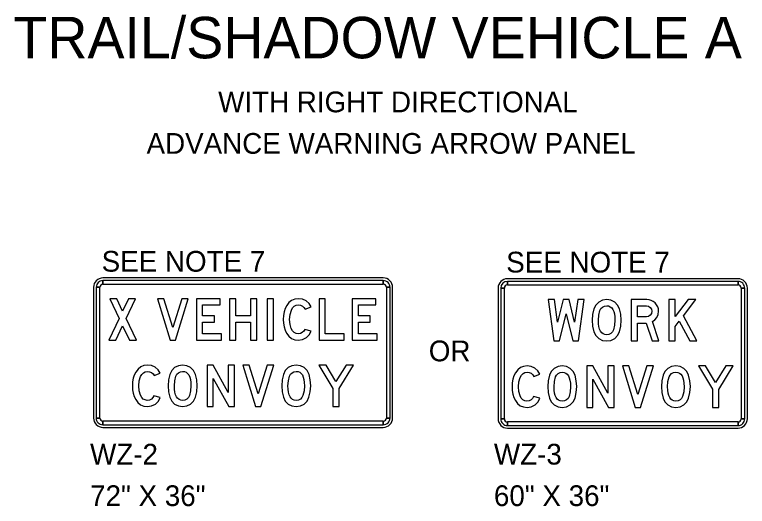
# Model space of a CAD drawing. Extents: x 1807779 to 1818251, y 673292 to 678849.
# Drawn here: x 1817413.4 to 1817625.1, y 677044.8 to 677187 of the extents above; entities that cross this region are included whole.
import ezdxf

# ---------------------------------------------------------------- set-up
doc = ezdxf.new("R2010")
doc.units = 0
doc.layers.add('DSN_RDWY_Drive', color=7, linetype='Continuous')

msp = doc.modelspace()

# ---------------------------------------------------------------- linework, layer by layer
at = {"layer": 'DSN_RDWY_Drive'}
for p, q in [((1817519.9, 677110.88), (1817438.9, 677110.88)), ((1817438.9, 677109.08), (1817438.9, 677110.13)), ((1817519.9, 677110.13), (1817519.9, 677109.08)), ((1817622.37, 677110.65), (1817555.77, 677110.65)), ((1817555.77, 677108.85), (1817555.77, 677109.9)), ((1817622.37, 677109.9), (1817622.37, 677108.85)), ((1817436.2, 677108.18), (1817436.2, 677070.38)), ((1817436.95, 677108.18), (1817438, 677108.18)), ((1817520.8, 677108.18), (1817521.85, 677108.18)), ((1817522.6, 677070.38), (1817522.6, 677108.18)), ((1817553.07, 677107.95), (1817553.07, 677070.15)), ((1817553.82, 677107.95), (1817554.87, 677107.95)), ((1817623.27, 677107.95), (1817624.32, 677107.95)), ((1817625.07, 677070.15), (1817625.07, 677107.95)), ((1817438, 677070.38), (1817436.95, 677070.38)), ((1817438.9, 677068.43), (1817438.9, 677069.48)), ((1817519.9, 677069.48), (1817519.9, 677068.43)), ((1817521.85, 677070.38), (1817520.8, 677070.38)), ((1817554.87, 677070.15), (1817553.82, 677070.15)), ((1817555.77, 677068.2), (1817555.77, 677069.25)), ((1817622.37, 677069.25), (1817622.37, 677068.2)), ((1817624.32, 677070.15), (1817623.27, 677070.15)), ((1817438.9, 677067.68), (1817519.9, 677067.68)), ((1817555.77, 677067.45), (1817622.37, 677067.45))]:
    msp.add_line(p, q, dxfattribs=at)
for points in [[(1817519.9, 677110.13), (1817438.9, 677110.13), (1817438.9, 677109.08), (1817519.9, 677109.08), (1817519.9, 677110.13)], [(1817622.37, 677109.9), (1817555.77, 677109.9), (1817555.77, 677108.85), (1817622.37, 677108.85), (1817622.37, 677109.9)], [(1817436.95, 677108.18), (1817436.95, 677070.38), (1817438, 677070.38), (1817438, 677108.18), (1817436.95, 677108.18)], [(1817521.85, 677070.38), (1817521.85, 677108.18), (1817520.8, 677108.18), (1817520.8, 677070.38), (1817521.85, 677070.38)], [(1817553.82, 677107.95), (1817553.82, 677070.15), (1817554.87, 677070.15), (1817554.87, 677107.95), (1817553.82, 677107.95)], [(1817624.32, 677070.15), (1817624.32, 677107.95), (1817623.27, 677107.95), (1817623.27, 677070.15), (1817624.32, 677070.15)], [(1817448.6, 677092.88), (1817445.61, 677099.16), (1817448.35, 677104.88), (1817446.34, 677104.88), (1817444.6, 677101.26), (1817442.88, 677104.88), (1817440.87, 677104.88), (1817443.6, 677099.15), (1817440.59, 677092.88), (1817442.59, 677092.88), (1817444.6, 677097.05), (1817446.59, 677092.88)], [(1817463.58, 677104.88), (1817461.69, 677104.88), (1817459.11, 677096.59), (1817456.54, 677104.88), (1817454.65, 677104.88), (1817458.37, 677092.88), (1817459.86, 677092.88)], [(1817473.15, 677094.69), (1817467.71, 677094.69), (1817467.71, 677098.09), (1817471.11, 677098.09), (1817471.11, 677099.9), (1817467.71, 677099.9), (1817467.71, 677103.07), (1817472.79, 677103.07), (1817472.79, 677104.88), (1817465.9, 677104.88), (1817465.9, 677092.88), (1817473.15, 677092.88)], [(1817483.38, 677092.88), (1817483.38, 677104.88), (1817481.57, 677104.88), (1817481.57, 677099.9), (1817477.27, 677099.9), (1817477.27, 677104.88), (1817475.46, 677104.88), (1817475.46, 677092.88), (1817477.27, 677092.88), (1817477.27, 677098.09), (1817481.57, 677098.09), (1817481.57, 677092.88)], [(1817488.15, 677092.88), (1817488.15, 677104.88), (1817486.34, 677104.88), (1817486.34, 677092.88)], [(1817499.03, 677095.54), (1817497.22, 677096), (1817496.95, 677095.48), (1817496.51, 677095.06), (1817495.95, 677094.78), (1817495.32, 677094.69), (1817494.69, 677094.79), (1817494.15, 677095.07), (1817493.7, 677095.55), (1817493.33, 677096.22), (1817492.96, 677097.45), (1817492.84, 677098.88), (1817492.96, 677100.31), (1817493.34, 677101.55), (1817493.72, 677102.21), (1817494.19, 677102.69), (1817494.74, 677102.97), (1817495.38, 677103.07), (1817495.98, 677102.98), (1817496.53, 677102.73), (1817496.98, 677102.34), (1817497.29, 677101.84), (1817499.03, 677102.52), (1817498.45, 677103.48), (1817497.59, 677104.23), (1817496.55, 677104.72), (1817495.41, 677104.88), (1817494.35, 677104.75), (1817493.43, 677104.38), (1817492.65, 677103.75), (1817491.99, 677102.88), (1817491.57, 677102.01), (1817491.27, 677101.06), (1817491.09, 677100.01), (1817491.02, 677098.89), (1817491.08, 677097.76), (1817491.26, 677096.72), (1817491.56, 677095.77), (1817491.98, 677094.9), (1817492.62, 677094.01), (1817493.4, 677093.39), (1817494.31, 677093), (1817495.35, 677092.88), (1817496.57, 677093.06), (1817497.67, 677093.62), (1817498.52, 677094.47)], [(1817508.59, 677092.88), (1817508.59, 677094.69), (1817503.15, 677094.69), (1817503.15, 677104.88), (1817501.34, 677104.88), (1817501.34, 677092.88)], [(1817518.15, 677094.69), (1817512.71, 677094.69), (1817512.71, 677098.09), (1817516.11, 677098.09), (1817516.11, 677099.9), (1817512.71, 677099.9), (1817512.71, 677103.07), (1817517.79, 677103.07), (1817517.79, 677104.88), (1817510.9, 677104.88), (1817510.9, 677092.88), (1817518.15, 677092.88)], [(1817577.93, 677104.64), (1817576.1, 677104.64), (1817575.18, 677098.07), (1817573.59, 677104.64), (1817571.84, 677104.64), (1817570.26, 677098.06), (1817569.34, 677104.64), (1817567.51, 677104.64), (1817569.19, 677092.65), (1817570.82, 677092.65), (1817572.72, 677100.54), (1817574.62, 677092.65), (1817576.25, 677092.65)], [(1817588.63, 677098.65), (1817588.51, 677100.36), (1817588.14, 677101.97), (1817587.6, 677103.05), (1817586.74, 677103.91), (1817585.66, 677104.46), (1817584.44, 677104.64), (1817583.22, 677104.46), (1817582.14, 677103.91), (1817581.28, 677103.05), (1817580.74, 677101.96), (1817580.37, 677100.35), (1817580.25, 677098.65), (1817580.37, 677096.95), (1817580.74, 677095.34), (1817581.28, 677094.25), (1817582.14, 677093.39), (1817583.22, 677092.83), (1817584.44, 677092.65), (1817585.65, 677092.83), (1817586.74, 677093.38), (1817587.59, 677094.24), (1817588.13, 677095.32), (1817588.5, 677096.93)], [(1817599.51, 677092.65), (1817597.62, 677098.25), (1817598.36, 677098.77), (1817598.93, 677099.49), (1817599.3, 677100.35), (1817599.43, 677101.27), (1817599.36, 677101.94), (1817599.18, 677102.56), (1817598.87, 677103.13), (1817598.43, 677103.65), (1817597.9, 677104.09), (1817597.33, 677104.4), (1817596.7, 677104.58), (1817596.03, 677104.64), (1817591.5, 677104.64), (1817591.5, 677092.65), (1817593.31, 677092.65), (1817593.31, 677097.85), (1817595.83, 677097.85), (1817597.6, 677092.65)], [(1817610.51, 677092.65), (1817606.61, 677099.96), (1817610.22, 677104.64), (1817607.93, 677104.64), (1817604.19, 677099.78), (1817604.19, 677104.64), (1817602.38, 677104.64), (1817602.38, 677092.65), (1817604.19, 677092.65), (1817604.19, 677096.82), (1817605.4, 677098.38), (1817608.46, 677092.65)], [(1817586.82, 677098.64), (1817586.71, 677097.19), (1817586.4, 677095.83), (1817586.11, 677095.27), (1817585.66, 677094.83), (1817585.09, 677094.55), (1817584.45, 677094.46), (1817583.89, 677094.52), (1817583.4, 677094.72), (1817582.99, 677095.04), (1817582.66, 677095.5), (1817582.4, 677096.09), (1817582.21, 677096.81), (1817582.1, 677097.66), (1817582.07, 677098.64), (1817582.17, 677100.1), (1817582.49, 677101.45), (1817582.78, 677102.01), (1817583.23, 677102.46), (1817583.8, 677102.74), (1817584.45, 677102.83), (1817585, 677102.77), (1817585.48, 677102.57), (1817585.89, 677102.24), (1817586.23, 677101.79), (1817586.48, 677101.2), (1817586.67, 677100.48), (1817586.78, 677099.62)], [(1817593.31, 677099.66), (1817593.31, 677102.83), (1817595.95, 677102.83), (1817596.53, 677102.71), (1817597.02, 677102.36), (1817597.35, 677101.85), (1817597.46, 677101.25), (1817597.35, 677100.64), (1817597.02, 677100.13), (1817596.53, 677099.78), (1817595.95, 677099.66)], [(1817455.44, 677076.34), (1817453.62, 677076.8), (1817453.36, 677076.28), (1817452.92, 677075.86), (1817452.35, 677075.58), (1817451.73, 677075.49), (1817451.1, 677075.59), (1817450.56, 677075.87), (1817450.1, 677076.35), (1817449.73, 677077.02), (1817449.36, 677078.25), (1817449.24, 677079.68), (1817449.37, 677081.12), (1817449.75, 677082.35), (1817450.13, 677083.01), (1817450.59, 677083.49), (1817451.14, 677083.77), (1817451.79, 677083.87), (1817452.39, 677083.78), (1817452.93, 677083.54), (1817453.39, 677083.14), (1817453.7, 677082.64), (1817455.44, 677083.32), (1817454.85, 677084.29), (1817454, 677085.04), (1817452.96, 677085.52), (1817451.82, 677085.68), (1817450.76, 677085.55), (1817449.84, 677085.18), (1817449.05, 677084.55), (1817448.4, 677083.68), (1817447.97, 677082.81), (1817447.67, 677081.86), (1817447.49, 677080.82), (1817447.43, 677079.69), (1817447.49, 677078.56), (1817447.67, 677077.52), (1817447.96, 677076.57), (1817448.39, 677075.7), (1817449.03, 677074.82), (1817449.8, 677074.19), (1817450.71, 677073.8), (1817451.76, 677073.68), (1817452.98, 677073.86), (1817454.07, 677074.42), (1817454.93, 677075.27)], [(1817466.12, 677079.69), (1817466, 677081.4), (1817465.63, 677083), (1817465.09, 677084.08), (1817464.23, 677084.94), (1817463.14, 677085.49), (1817461.92, 677085.68), (1817460.7, 677085.49), (1817459.62, 677084.94), (1817458.77, 677084.08), (1817458.23, 677082.99), (1817457.86, 677081.39), (1817457.74, 677079.69), (1817457.86, 677077.99), (1817458.23, 677076.38), (1817458.77, 677075.29), (1817459.62, 677074.43), (1817460.7, 677073.87), (1817461.92, 677073.68), (1817463.14, 677073.86), (1817464.22, 677074.42), (1817465.08, 677075.27), (1817465.62, 677076.36), (1817465.99, 677077.97)], [(1817476.92, 677073.68), (1817476.92, 677085.68), (1817475.11, 677085.68), (1817475.11, 677077.79), (1817470.73, 677085.68), (1817468.99, 677085.68), (1817468.99, 677073.68), (1817470.8, 677073.68), (1817470.8, 677081.82), (1817475.32, 677073.68)], [(1817488.24, 677085.68), (1817486.35, 677085.68), (1817483.77, 677077.39), (1817481.2, 677085.68), (1817479.31, 677085.68), (1817483.02, 677073.68), (1817484.51, 677073.68)], [(1817498.93, 677079.69), (1817498.81, 677081.4), (1817498.44, 677083), (1817497.9, 677084.08), (1817497.04, 677084.94), (1817495.96, 677085.49), (1817494.74, 677085.68), (1817493.52, 677085.49), (1817492.44, 677084.94), (1817491.58, 677084.08), (1817491.04, 677082.99), (1817490.68, 677081.39), (1817490.56, 677079.69), (1817490.68, 677077.99), (1817491.04, 677076.38), (1817491.58, 677075.29), (1817492.44, 677074.43), (1817493.52, 677073.87), (1817494.74, 677073.68), (1817495.95, 677073.86), (1817497.04, 677074.42), (1817497.89, 677075.27), (1817498.43, 677076.36), (1817498.8, 677077.97)], [(1817511.3, 677085.68), (1817509.17, 677085.68), (1817506.23, 677080.89), (1817503.35, 677085.68), (1817501.24, 677085.68), (1817505.32, 677078.94), (1817505.32, 677073.68), (1817507.13, 677073.68), (1817507.13, 677078.89)], [(1817565.11, 677076.11), (1817563.29, 677076.57), (1817563.02, 677076.04), (1817562.58, 677075.62), (1817562.02, 677075.35), (1817561.4, 677075.26), (1817560.77, 677075.35), (1817560.23, 677075.64), (1817559.77, 677076.12), (1817559.4, 677076.78), (1817559.03, 677078.02), (1817558.91, 677079.44), (1817559.03, 677080.88), (1817559.41, 677082.12), (1817559.79, 677082.78), (1817560.26, 677083.25), (1817560.81, 677083.54), (1817561.46, 677083.63), (1817562.05, 677083.55), (1817562.6, 677083.3), (1817563.06, 677082.91), (1817563.37, 677082.41), (1817565.11, 677083.09), (1817564.52, 677084.05), (1817563.66, 677084.8), (1817562.62, 677085.28), (1817561.48, 677085.44), (1817560.43, 677085.32), (1817559.51, 677084.94), (1817558.72, 677084.32), (1817558.06, 677083.44), (1817557.64, 677082.58), (1817557.34, 677081.62), (1817557.16, 677080.58), (1817557.1, 677079.45), (1817557.15, 677078.32), (1817557.33, 677077.28), (1817557.63, 677076.33), (1817558.05, 677075.47), (1817558.69, 677074.58), (1817559.47, 677073.95), (1817560.38, 677073.57), (1817561.42, 677073.45), (1817562.64, 677073.63), (1817563.74, 677074.18), (1817564.6, 677075.04)], [(1817575.79, 677079.45), (1817575.66, 677081.16), (1817575.3, 677082.77), (1817574.76, 677083.85), (1817573.9, 677084.71), (1817572.81, 677085.26), (1817571.59, 677085.44), (1817570.37, 677085.26), (1817569.29, 677084.71), (1817568.44, 677083.85), (1817567.9, 677082.76), (1817567.53, 677081.15), (1817567.41, 677079.45), (1817567.53, 677077.75), (1817567.9, 677076.14), (1817568.44, 677075.05), (1817569.29, 677074.19), (1817570.37, 677073.63), (1817571.59, 677073.45), (1817572.81, 677073.63), (1817573.89, 677074.18), (1817574.75, 677075.04), (1817575.29, 677076.12), (1817575.66, 677077.73)], [(1817586.58, 677073.45), (1817586.58, 677085.44), (1817584.77, 677085.44), (1817584.77, 677077.56), (1817580.4, 677085.44), (1817578.66, 677085.44), (1817578.66, 677073.45), (1817580.47, 677073.45), (1817580.47, 677081.59), (1817584.99, 677073.45)], [(1817597.91, 677085.44), (1817596.01, 677085.44), (1817593.44, 677077.15), (1817590.87, 677085.44), (1817588.97, 677085.44), (1817592.69, 677073.45), (1817594.18, 677073.45)], [(1817608.6, 677079.45), (1817608.48, 677081.16), (1817608.11, 677082.77), (1817607.57, 677083.85), (1817606.71, 677084.71), (1817605.62, 677085.26), (1817604.4, 677085.44), (1817603.18, 677085.26), (1817602.1, 677084.71), (1817601.25, 677083.85), (1817600.71, 677082.76), (1817600.34, 677081.15), (1817600.22, 677079.45), (1817600.34, 677077.75), (1817600.71, 677076.14), (1817601.25, 677075.05), (1817602.1, 677074.19), (1817603.18, 677073.63), (1817604.4, 677073.45), (1817605.62, 677073.63), (1817606.7, 677074.18), (1817607.56, 677075.04), (1817608.1, 677076.12), (1817608.47, 677077.73)], [(1817620.97, 677085.44), (1817618.84, 677085.44), (1817615.9, 677080.65), (1817613.02, 677085.44), (1817610.91, 677085.44), (1817614.99, 677078.7), (1817614.99, 677073.45), (1817616.8, 677073.45), (1817616.8, 677078.65)], [(1817464.31, 677079.68), (1817464.2, 677078.22), (1817463.88, 677076.87), (1817463.59, 677076.3), (1817463.14, 677075.86), (1817462.58, 677075.58), (1817461.94, 677075.49), (1817461.38, 677075.55), (1817460.89, 677075.75), (1817460.48, 677076.08), (1817460.15, 677076.54), (1817459.89, 677077.13), (1817459.7, 677077.85), (1817459.59, 677078.7), (1817459.55, 677079.68), (1817459.66, 677081.13), (1817459.98, 677082.48), (1817460.26, 677083.05), (1817460.71, 677083.49), (1817461.28, 677083.77), (1817461.94, 677083.87), (1817462.49, 677083.8), (1817462.97, 677083.61), (1817463.38, 677083.28), (1817463.71, 677082.82), (1817463.97, 677082.23), (1817464.16, 677081.51), (1817464.27, 677080.66)], [(1817497.12, 677079.68), (1817497.01, 677078.22), (1817496.7, 677076.87), (1817496.41, 677076.3), (1817495.96, 677075.86), (1817495.39, 677075.58), (1817494.75, 677075.49), (1817494.19, 677075.55), (1817493.7, 677075.75), (1817493.29, 677076.08), (1817492.96, 677076.54), (1817492.7, 677077.13), (1817492.51, 677077.85), (1817492.4, 677078.7), (1817492.37, 677079.68), (1817492.47, 677081.13), (1817492.79, 677082.48), (1817493.08, 677083.05), (1817493.53, 677083.49), (1817494.1, 677083.77), (1817494.75, 677083.87), (1817495.3, 677083.8), (1817495.78, 677083.61), (1817496.19, 677083.28), (1817496.53, 677082.82), (1817496.78, 677082.23), (1817496.97, 677081.51), (1817497.08, 677080.66)], [(1817573.98, 677079.44), (1817573.87, 677077.99), (1817573.55, 677076.63), (1817573.26, 677076.07), (1817572.81, 677075.63), (1817572.25, 677075.35), (1817571.61, 677075.26), (1817571.04, 677075.32), (1817570.56, 677075.52), (1817570.15, 677075.84), (1817569.82, 677076.3), (1817569.55, 677076.89), (1817569.37, 677077.61), (1817569.26, 677078.46), (1817569.22, 677079.44), (1817569.33, 677080.9), (1817569.65, 677082.25), (1817569.93, 677082.81), (1817570.38, 677083.26), (1817570.95, 677083.54), (1817571.61, 677083.63), (1817572.16, 677083.57), (1817572.64, 677083.37), (1817573.05, 677083.04), (1817573.38, 677082.59), (1817573.64, 677082), (1817573.83, 677081.28), (1817573.94, 677080.42)], [(1817606.79, 677079.44), (1817606.68, 677077.99), (1817606.36, 677076.63), (1817606.07, 677076.07), (1817605.62, 677075.63), (1817605.06, 677075.35), (1817604.42, 677075.26), (1817603.86, 677075.32), (1817603.37, 677075.52), (1817602.96, 677075.84), (1817602.63, 677076.3), (1817602.37, 677076.89), (1817602.18, 677077.61), (1817602.07, 677078.46), (1817602.03, 677079.44), (1817602.14, 677080.9), (1817602.46, 677082.25), (1817602.74, 677082.81), (1817603.19, 677083.26), (1817603.76, 677083.54), (1817604.42, 677083.63), (1817604.97, 677083.57), (1817605.45, 677083.37), (1817605.86, 677083.04), (1817606.19, 677082.59), (1817606.45, 677082), (1817606.64, 677081.28), (1817606.75, 677080.42)], [(1817438.9, 677068.43), (1817519.9, 677068.43), (1817519.9, 677069.48), (1817438.9, 677069.48), (1817438.9, 677068.43)], [(1817555.77, 677068.2), (1817622.37, 677068.2), (1817622.37, 677069.25), (1817555.77, 677069.25), (1817555.77, 677068.2)]]:
    msp.add_lwpolyline(points, close=True, dxfattribs=at)
for centre, radius, start, end in [((1817438.9, 677108.18), 2.7, 90.0002, 179.9998), ((1817519.9, 677108.18), 2.7, 0, 90.0002), ((1817438.9, 677108.18), 1.95, 90.0002, 179.9998), ((1817438.9, 677108.18), 0.9, 90.0002, 179.9998), ((1817519.9, 677108.18), 1.95, 0, 90.0002), ((1817519.9, 677108.18), 0.9, 0, 90.0002), ((1817555.77, 677107.95), 2.7, 90.0002, 179.9998), ((1817555.77, 677107.95), 1.95, 90.0002, 179.9998), ((1817555.77, 677107.95), 0.9, 90.0002, 179.9998), ((1817622.37, 677107.95), 2.7, 0, 90.0002), ((1817622.37, 677107.95), 1.95, 0, 90.0002), ((1817622.37, 677107.95), 0.9, 0, 90.0002), ((1817438.9, 677070.38), 2.7, 179.9998, 270.0001), ((1817438.9, 677070.38), 1.95, 179.9998, 270.0001), ((1817438.9, 677070.38), 0.9, 179.9998, 270.0001), ((1817519.9, 677070.38), 2.7, 270.0001, 0.0003), ((1817519.9, 677070.38), 1.95, 270.0001, 0.0003), ((1817519.9, 677070.38), 0.9, 270.0001, 0.0003), ((1817555.77, 677070.15), 2.7, 179.9998, 270.0001), ((1817555.77, 677070.15), 1.95, 179.9998, 270.0001), ((1817555.77, 677070.15), 0.9, 179.9998, 270.0001), ((1817622.37, 677070.15), 2.7, 270.0001, 0.0003), ((1817622.37, 677070.15), 1.95, 270.0001, 0.0003), ((1817622.37, 677070.15), 0.9, 270.0001, 0.0003)]:
    msp.add_arc(centre, radius, start, end, dxfattribs=at)

# ---------------------------------------------------------------- texts
for s, height, p in [('TRAIL/SHADOW VEHICLE A', 12, (1817413.05, 677174.38)), ('WITH RIGHT DIRECTIONAL', 6, (1817472.2, 677158.78)), ('ADVANCE WARNING ARROW PANEL', 6, (1817451.51, 677146.78)), ('SEE NOTE 7 ', 6, (1817438.54, 677112.69)), ('SEE NOTE 7 ', 6, (1817555.41, 677112.45))]:
    msp.add_text(s, height=height, dxfattribs=at).set_placement(p)
for s, p in [('OR', (1817533.04, 677086.78)), ('WZ-2', (1817435.2, 677056.92)), ('WZ-3', (1817551.86, 677056.92)), ('72" X 36"', (1817435.2, 677044.92)), ('60" X 36"', (1817551.86, 677044.92))]:
    msp.add_text(s, height=6, rotation=0, dxfattribs=at).set_placement(p)

doc.saveas('drawing.dxf')
